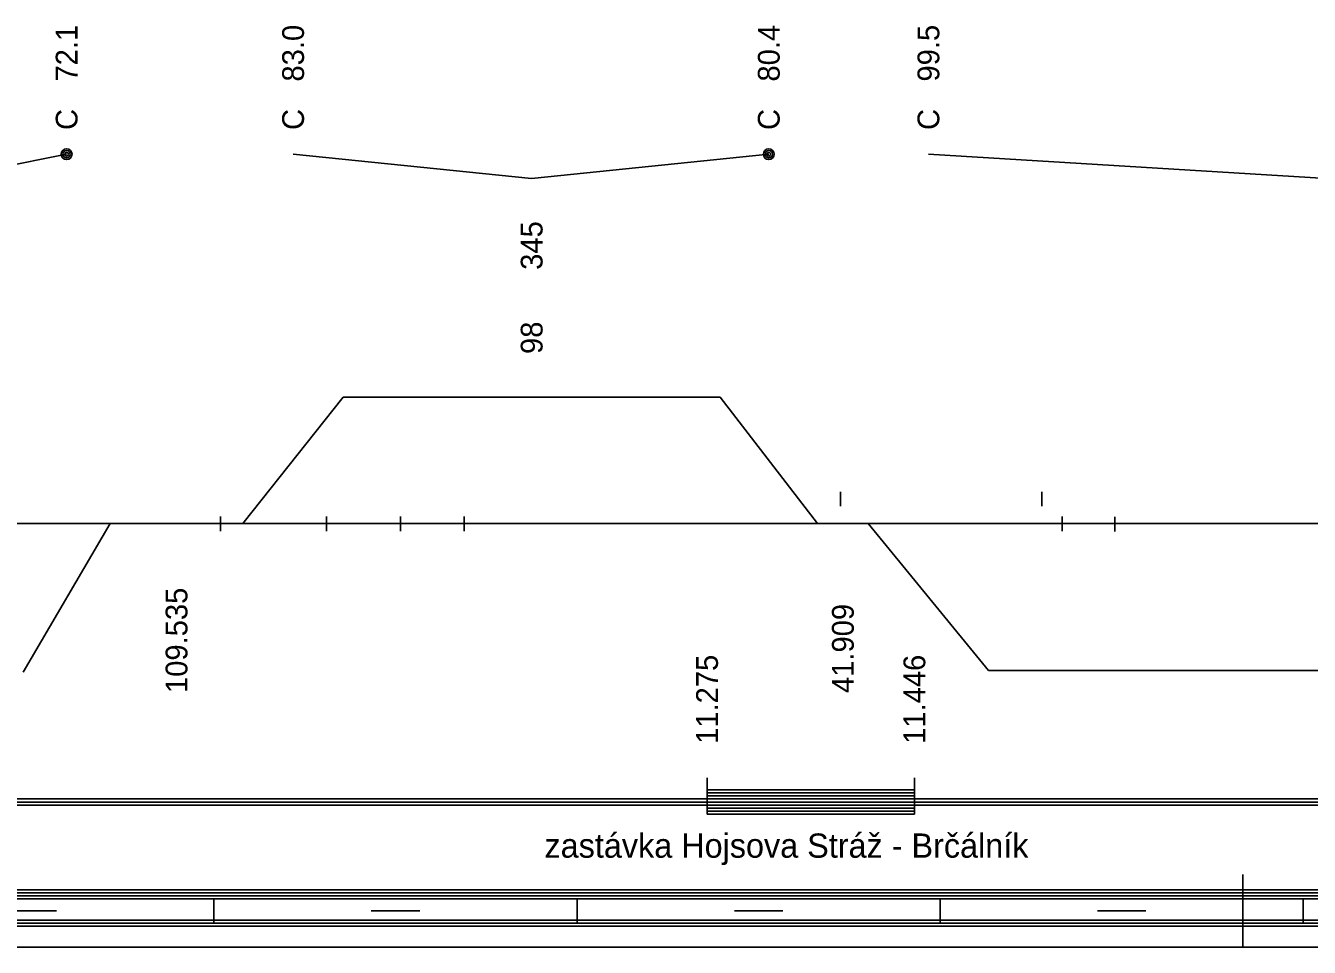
# Model space of a CAD drawing. Extents: x 2 to 10148, y 0 to 380.
# Drawn here: x 1369.4 to 1475.5, y 0 to 76.1 of the extents above; entities that cross this region are included whole.
import ezdxf

# ---------------------------------------------------------------- set-up
doc = ezdxf.new("R2010")
doc.units = 0
for name, color, linetype in [('KRIV1_CARA', 7, 'Continuous'), ('KRIV1_TEXT', 7, 'Continuous'), ('L_OBJEKTY_TEXT', 7, 'Continuous'), ('L_OBJEKTY_TVAR', 7, 'Continuous'), ('RAM', 7, 'Continuous'), ('STAN_CARA', 7, 'Continuous')]:
    doc.layers.add(name, color=color, linetype=linetype)

msp = doc.modelspace()

# ---------------------------------------------------------------- linework, layer by layer
for p, q in [((1436.76, 37.61), (1436.76, 36.42)), ((1453.39, 37.61), (1453.39, 36.42)), ((1385.54, 35.57), (1385.54, 34.38)), ((1394.29, 35.57), (1394.29, 34.38)), ((1400.42, 35.57), (1400.42, 34.38)), ((1405.67, 35.57), (1405.67, 34.38)), ((1455.08, 35.57), (1455.08, 34.38)), ((1459.44, 35.54), (1459.44, 34.35))]:
    msp.add_line(p, q)
at = {"layer": 'KRIV1_CARA'}
for p, q in [((1387.39, 35), (1395.69, 45.44)), ((1395.69, 45.44), (1426.82, 45.44)), ((1426.82, 45.44), (1434.86, 35)), ((1245.39, 35), (1850.83, 35)), ((1369.23, 22.71), (1376.44, 35)), ((1439.05, 35), (1449, 22.86)), ((1449, 22.86), (1504.85, 22.86))]:
    msp.add_line(p, q, dxfattribs=at)
at = {"layer": 'KRIV1_TEXT'}
for p, q in [((1362.86, 63.5), (1372.83, 65.5)), ((1411.25, 63.5), (1391.54, 65.5)), ((1411.25, 63.5), (1430.84, 65.5)), ((1476.92, 63.5), (1444.03, 65.5))]:
    msp.add_line(p, q, dxfattribs=at)
for centre, radius in [((1372.83, 65.5), 0.45), ((1372.83, 65.5), 0.3), ((1430.84, 65.5), 0.45), ((1430.84, 65.5), 0.3), ((1372.83, 65.5), 0.15), ((1430.84, 65.5), 0.15)]:
    msp.add_circle(centre, radius, dxfattribs=at)
at = {"layer": 'L_OBJEKTY_TVAR'}
for p, q in [((1425.74, 11), (1425.74, 14)), ((1442.87, 11), (1442.87, 14)), ((1425.74, 13), (1442.87, 13)), ((1425.74, 12.75), (1442.87, 12.75)), ((1425.74, 12.5), (1442.87, 12.5)), ((1425.74, 12.25), (1442.87, 12.25)), ((1425.74, 12), (1442.87, 12)), ((1425.74, 11.75), (1442.87, 11.75)), ((1425.74, 11.5), (1442.87, 11.5)), ((1425.74, 11.25), (1442.87, 11.25)), ((1425.74, 11), (1442.87, 11))]:
    msp.add_line(p, q, dxfattribs=at)
at = {"layer": 'RAM'}
for p, q in [((1470, 0), (1470, 6)), ((1245.39, 4.75), (1850.83, 4.75)), ((1245.39, 4.5), (1850.83, 4.5)), ((1245.39, 4.25), (1850.83, 4.25)), ((1245.39, 4), (1850.83, 4)), ((1385, 2), (1385, 4)), ((1415, 2), (1415, 4)), ((1445, 2), (1445, 4)), ((1475, 2), (1475, 4)), ((1245.39, 2.25), (1850.83, 2.25)), ((1368, 3), (1372, 3)), ((1398, 3), (1402, 3)), ((1428, 3), (1432, 3)), ((1458, 3), (1462, 3)), ((1245.39, 2), (1850.83, 2)), ((1245.39, 1.75), (1850.83, 1.75)), ((1245.39, 0), (1850.83, 0))]:
    msp.add_line(p, q, dxfattribs=at)
at = {"layer": 'STAN_CARA'}
for p, q in [((1299.78, 12.25), (1796.78, 12.25)), ((1299.78, 12), (1796.78, 12)), ((1299.78, 12), (1796.78, 12)), ((1299.78, 11.75), (1796.78, 11.75))]:
    msp.add_line(p, q, dxfattribs=at)

# ---------------------------------------------------------------- texts
at = {"layer": 'KRIV1_TEXT'}
for s, p in [('72.1', (1373.73, 71.5)), ('83.0', (1392.44, 71.5)), ('80.4', (1431.74, 71.5)), ('99.5', (1444.93, 71.5)), ('C', (1373.73, 67.5)), ('C', (1392.44, 67.5)), ('C', (1431.74, 67.5)), ('C', (1444.93, 67.5)), ('345', (1412.15, 55.95)), ('98', (1412.15, 49)), ('109.535', (1382.81, 21)), ('41.909', (1437.86, 21))]:
    msp.add_text(s, height=1.8, rotation=90, dxfattribs=at).set_placement(p)
at = {"layer": 'L_OBJEKTY_TEXT'}
for s, p in [('11.275', (1426.64, 16.8)), ('11.446', (1443.77, 16.8))]:
    msp.add_text(s, height=1.8, rotation=90, dxfattribs=at).set_placement(p)
msp.add_text('zastávka Hojsova Stráž - Brčálník', height=2, dxfattribs=at).set_placement((1412.31, 7.4))

doc.saveas('drawing.dxf')
